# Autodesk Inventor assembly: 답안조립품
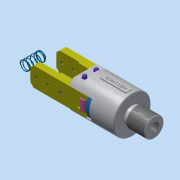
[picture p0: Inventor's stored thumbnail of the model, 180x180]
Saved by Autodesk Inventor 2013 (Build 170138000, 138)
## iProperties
Created: 2019-02
Part Number: 답안조립품
Document SubType Name: Assembly
Designer: Administrator
Author: Administrator
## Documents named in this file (11)
- C:\Users\Administrator\Desktop\490207V1009\답안조립품.iam
- C:\Users\Administrator\Desktop\490207V1009\1-본체.ipt
- C:\Users\Administrator\Desktop\490207V1009\O-링.ipt
- C:\Users\Administrator\Desktop\490207V1009\피스톤.ipt
- C:\Users\Administrator\Desktop\490207V1009\부시.ipt
- C:\Users\Administrator\Desktop\490207V1009\평행핀 6x28.ipt
- C:\Users\Administrator\Desktop\490207V1009\핀.ipt
- C:\Users\Administrator\Desktop\490207V1009\핑거.ipt
- C:\Users\Administrator\Desktop\490207V1009\E-링.ipt
- C:\Users\Administrator\Desktop\490207V1009\가이드핀.ipt
- C:\Users\Administrator\Desktop\490207V1009\스프링.ipt
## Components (14 placed, 7 different names)
1. 1-본체:1 — 각도:1
2. O-링:1
3. 피스톤:1 — 각도:1
4. O-링:2
5. 핀:1
6. 핀:2
7. 핑거:1
8. 핑거:2
9. E-링:1
10. E-링:2
11. E-링:4
12. E-링:5
13. 가이드핀:1
14. 가이드핀:2
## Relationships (1: Angle 1)
- 각도:1 [Angle]: 1-본체:1 ↔ 피스톤:1
